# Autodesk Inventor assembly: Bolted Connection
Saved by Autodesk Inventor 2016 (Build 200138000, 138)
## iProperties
Created: 2016-01
Part Number: Bolted Connection
Document SubType Name: Assembly
Designer: Black Falcon
ClientObjectVersion: 1
Author: Black Falcon
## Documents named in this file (2)
- E:\Learning Inventor\Belt Friction Apparatus\Final Assembly\Design Accelerator\Bolted Connection4.iam
- C:\Users\Black Falcon\Documents\Inventor\Content Center Files\R2016\en-US\ANSI ASME B18.2.1(2)\ANSI_ASME B18.2.1 - 5_16-18 UNC - 1.25(2).ipt
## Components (1 placed, 1 different names)
1. Hex Bolt - Inch 5/16-18 UNC - 1.25:1
